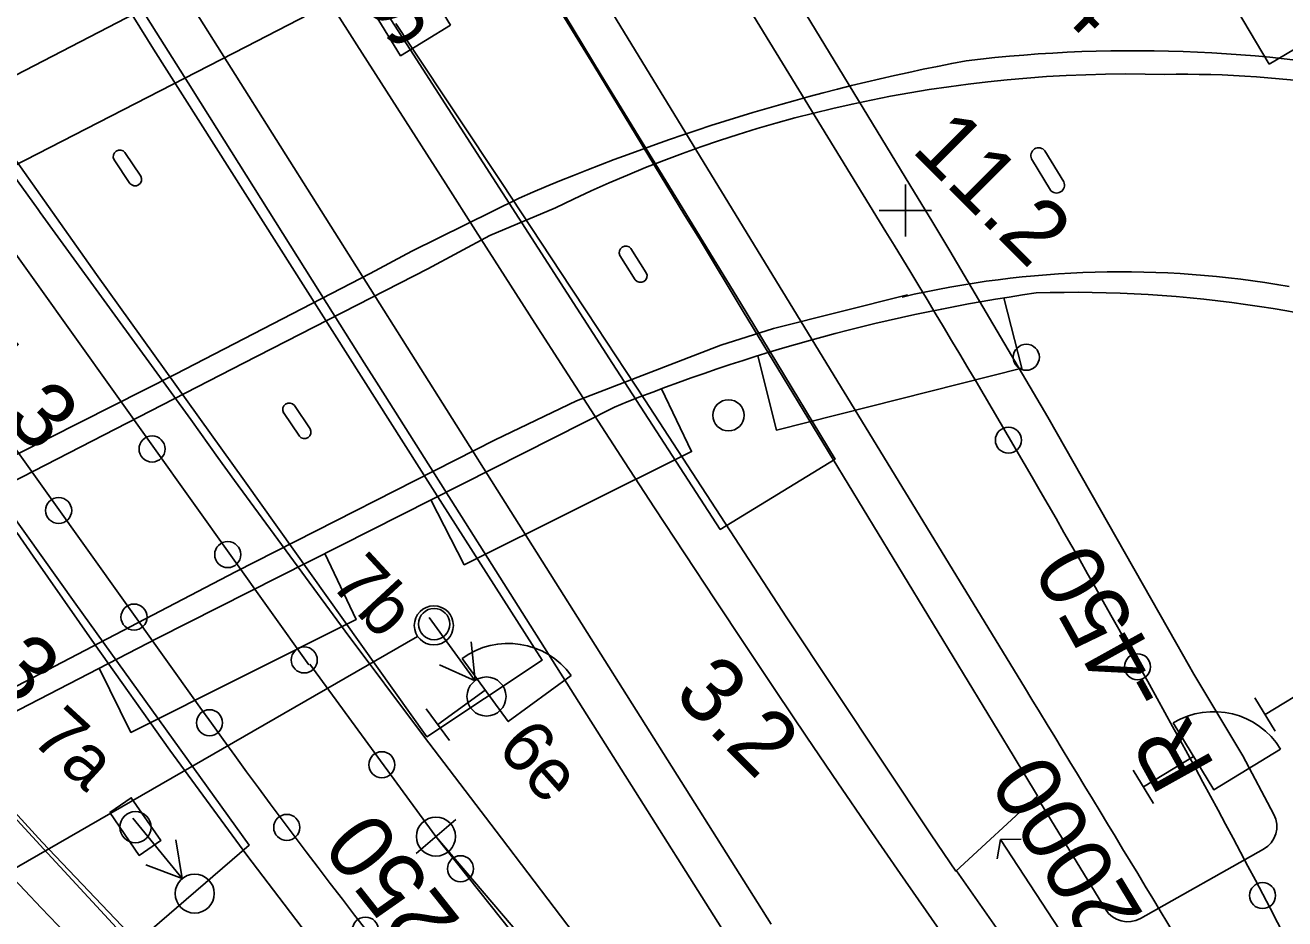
# Model space of a CAD drawing. Extents: x 1596643 to 1597288, y 13057194 to 13057957.
# Drawn here: x 1596850.68 to 1596899.03, y 13057506.23 to 13057540.55 of the extents above; entities that cross this region are included whole.
import ezdxf

# ---------------------------------------------------------------- set-up
doc = ezdxf.new("R2010")
doc.units = 0
for name, color, linetype in [('A Spårgeometri T', 7, 'Continuous'), ('A spårmitt L', 7, 'Continuous'), ('B Fsk P', 7, 'Continuous'), ('B kabelbrunn mindre än 150 cm NK P', 7, 'Continuous'), ('B växel linjevikt 0 L', 7, 'Continuous'), ('BAS bro ej def L', 7, 'Continuous'), ('BAS byggnad anläggning L', 7, 'Continuous'), ('BAS Level 14', 7, 'Continuous'), ('BAS Level 15', 7, 'Continuous'), ('BAS Level 16', 7, 'Continuous'), ('BAS markytetext T', 7, 'Continuous'), ('BAS skärmtak L', 7, 'Continuous'), ('BAS väg-bro pelare stöd L', 7, 'Continuous'), ('BAS vägbanekant L', 7, 'Continuous'), ('D Plattform L', 7, 'Continuous'), ('D plattform lastkaj -takstöd P', 7, 'Continuous'), ('D plattform tak L', 7, 'Continuous'), ('E ktlbrygga L', 7, 'Continuous'), ('E ktlstolpe normal centrum P', 7, 'Continuous'), ('E ktlstolpe omvriden centrum P', 7, 'Continuous'), ('E ktlstolpe T', 7, 'Continuous'), ('F dvärgsignal fristående P', 7, 'Continuous'), ('F tavla fristående P', 7, 'Continuous')]:
    doc.layers.add(name, color=color, linetype=linetype)

msp = doc.modelspace()

# ---------------------------------------------------------------- linework, layer by layer
at = {"layer": 'A spårmitt L'}
for p, q in [((1596861.568, 13057515.983), (1596783.022, 13057626.053)), ((1596889.034, 13057515.129), (1596838.504, 13057597.87)), ((1596879.311, 13057506.034), (1596843.07, 13057563.495))]:
    msp.add_line(p, q, dxfattribs=at)
for points in [[(1596857.385, 13057514.365), (1596753.204, 13057660.429)], [(1596883.716, 13057532.617), (1596844.805, 13057596.132)], [(1596886.686, 13057504.512), (1596885.471, 13057506.242), (1596884.265, 13057507.977), (1596883.065, 13057509.717), (1596881.872, 13057511.462), (1596880.686, 13057513.212), (1596879.507, 13057514.966), (1596878.333, 13057516.723), (1596877.164, 13057518.484), (1596876, 13057520.249), (1596874.841, 13057522.016), (1596873.686, 13057523.786), (1596872.535, 13057525.559), (1596871.387, 13057527.334), (1596870.242, 13057529.11), (1596869.099, 13057530.889), (1596867.959, 13057532.668), (1596866.82, 13057534.449), (1596865.683, 13057536.23), (1596864.546, 13057538.012), (1596863.41, 13057539.794), (1596846.221, 13057566.757)], [(1596861.603, 13057516.009), (1596866.442, 13057509.391), (1596878.849, 13057493.781), (1596895.097, 13057475.302), (1596900.34, 13057469.714), (1596931.231, 13057437.468), (1596933.8, 13057434.835)]]:
    msp.add_lwpolyline(points, dxfattribs=at)
for centre, radius, start, end in [((1597214.65, 13057850.135), 500, 218.04271, 224.75231), ((1596499.999, 13057297.54), 450, 26.52378, 31.49284), ((1597037.43, 13057725.326), 301.08, 223.02589, 237.32659), ((1595182.157, 13056472.741), 2000, 30.900492, 31.412375), ((1597060.917, 13057659.535), 250, 215.49853, 221.11206)]:
    msp.add_arc(centre, radius, start, end, dxfattribs=at)
at = {"layer": 'B Fsk P'}
msp.add_circle((1596866.447, 13057509.394), 0.75, dxfattribs=at)
msp.add_circle((1596866.447, 13057509.394), 0.75, dxfattribs=at)
at = {"layer": 'B kabelbrunn mindre än 150 cm NK P'}
msp.add_circle((1596889.108, 13057527.796), 0.5, dxfattribs=at)
msp.add_circle((1596889.108, 13057527.796), 0.5, dxfattribs=at)
at = {"layer": 'B växel linjevikt 0 L'}
for p, q in [((1596867.207, 13057510.044), (1596865.687, 13057508.744)), ((1596867.207, 13057510.044), (1596865.687, 13057508.744)), ((1596866.447, 13057509.394), (1596882.884, 13057490.154)), ((1596866.447, 13057509.394), (1596882.884, 13057490.154))]:
    msp.add_line(p, q, dxfattribs=at)
at = {"layer": 'BAS bro ej def L'}
for points in [[(1596943.383, 13057586.288), (1596918.209, 13057573.372), (1596902.266, 13057565.204), (1596883.836, 13057555.789), (1596868.629, 13057548.018), (1596857.404, 13057542.31), (1596846.034, 13057536.411), (1596835.657, 13057531.108), (1596827.266, 13057526.827), (1596817.271, 13057521.926), (1596816.146, 13057521.371), (1596813.704, 13057520.386), (1596810.367, 13057519.363)], [(1596873.3, 13057525.881), (1596855.752, 13057517.013), (1596837.576, 13057507.614), (1596820.661, 13057499.012), (1596812.839, 13057495.445), (1596806.321, 13057492.938), (1596797.787, 13057490.834), (1596791.903, 13057490.118), (1596786.013, 13057489.635), (1596782.527, 13057489.62), (1596780.068, 13057489.652), (1596778.301, 13057489.746), (1596776.535, 13057489.911), (1596771.663, 13057490.412), (1596770.466, 13057490.58)]]:
    msp.add_lwpolyline(points, dxfattribs=at)
for centre, radius, start, end in [((1596899.22, 13057462.24), 68.718, 98.1426, 112.16031), ((1596890.993, 13057483.825), 46.464, 70.6568, 91.8562)]:
    msp.add_arc(centre, radius, start, end, dxfattribs=at)
at = {"layer": 'BAS byggnad anläggning L'}
for points in [[(1596898.432, 13057539.054), (1596892.999, 13057548.2)], [(1596898.432, 13057539.054), (1596902.944, 13057541.738), (1596899.196, 13057548.047)]]:
    msp.add_lwpolyline(points, dxfattribs=at)
at = {"layer": 'BAS Level 14'}
for p, q in [((1596867.947, 13057515.378), (1596866.187, 13057517.808)), ((1596867.947, 13057515.378), (1596866.187, 13057517.808)), ((1596867.947, 13057515.378), (1596867.793, 13057516.87)), ((1596867.947, 13057515.378), (1596867.793, 13057516.87)), ((1596867.947, 13057515.378), (1596866.578, 13057515.991)), ((1596867.947, 13057515.378), (1596866.578, 13057515.991)), ((1596856.71, 13057507.783), (1596854.808, 13057510.102)), ((1596856.71, 13057507.783), (1596854.808, 13057510.102)), ((1596856.71, 13057507.783), (1596856.466, 13057509.263)), ((1596856.71, 13057507.783), (1596856.466, 13057509.263)), ((1596856.71, 13057507.783), (1596855.307, 13057508.312)), ((1596856.71, 13057507.783), (1596855.307, 13057508.312))]:
    msp.add_line(p, q, dxfattribs=at)
for centre in [(1596868.387, 13057514.771), (1596868.387, 13057514.771), (1596857.186, 13057507.203), (1596857.186, 13057507.203)]:
    msp.add_circle(centre, 0.75, dxfattribs=at)
at = {"layer": 'BAS Level 15'}
for centre in [(1596888.421, 13057524.613), (1596888.421, 13057524.613), (1596855.549, 13057524.274), (1596855.549, 13057524.274), (1596851.964, 13057521.911), (1596851.964, 13057521.911), (1596858.454, 13057520.219), (1596858.454, 13057520.219), (1596854.856, 13057517.82), (1596854.856, 13057517.82), (1596861.392, 13057516.173), (1596861.392, 13057516.173), (1596893.375, 13057515.912), (1596893.375, 13057515.912), (1596857.755, 13057513.763), (1596857.755, 13057513.763), (1596864.368, 13057512.15), (1596864.368, 13057512.15), (1596860.719, 13057509.745), (1596860.719, 13057509.745), (1596867.388, 13057508.158), (1596867.388, 13057508.158), (1596898.176, 13057507.128), (1596898.176, 13057507.128), (1596863.738, 13057505.801), (1596863.738, 13057505.801)]:
    msp.add_circle(centre, 0.5, dxfattribs=at)
at = {"layer": 'BAS Level 16'}
for q in [(1596884.465, 13057534.433), (1596884.465, 13057534.433), (1596883.465, 13057533.433), (1596883.465, 13057533.433), (1596885.465, 13057533.433), (1596884.465, 13057532.433), (1596885.465, 13057533.433), (1596884.465, 13057532.433)]:
    msp.add_line((1596884.465, 13057533.433), q, dxfattribs=at)
at = {"layer": 'BAS skärmtak L'}
for points in [[(1596888.241, 13057530.074), (1596888.937, 13057527.373), (1596879.514, 13057525.003), (1596878.798, 13057527.853)], [(1596875.104, 13057526.586), (1596876.257, 13057524.176), (1596867.535, 13057519.831), (1596866.251, 13057522.319)], [(1596862.187, 13057520.265), (1596863.387, 13057517.728), (1596854.736, 13057513.393), (1596853.523, 13057515.86)]]:
    msp.add_lwpolyline(points, dxfattribs=at)
at = {"layer": 'BAS väg-bro pelare stöd L'}
for p, q in [((1596854.508, 13057535.659), (1596855.114, 13057534.751)), ((1596889.821, 13057535.721), (1596890.543, 13057534.528)), ((1596854.092, 13057535.381), (1596854.698, 13057534.473)), ((1596889.308, 13057535.41), (1596890.03, 13057534.217)), ((1596874.098, 13057530.77), (1596873.51, 13057531.702)), ((1596873.933, 13057531.969), (1596874.521, 13057531.037)), ((1596861.012, 13057525.949), (1596861.621, 13057525.047)), ((1596860.598, 13057525.669), (1596861.207, 13057524.767))]:
    msp.add_line(p, q, dxfattribs=at)
for points in [[(1596854.508, 13057535.659), (1596855.114, 13057534.751)], [(1596889.821, 13057535.721), (1596890.543, 13057534.528)], [(1596854.092, 13057535.381), (1596854.698, 13057534.473)], [(1596889.308, 13057535.41), (1596890.03, 13057534.217)], [(1596874.098, 13057530.77), (1596873.51, 13057531.702)], [(1596873.933, 13057531.969), (1596874.521, 13057531.037)], [(1596861.012, 13057525.949), (1596861.621, 13057525.047)], [(1596860.598, 13057525.669), (1596861.207, 13057524.767)]]:
    msp.add_lwpolyline(points, dxfattribs=at)
for centre, radius, start, end in [((1596854.311, 13057535.503), 0.251, 38.4145, 209.0926), ((1596854.311, 13057535.503), 0.251, 38.3749, 209.1212), ((1596889.582, 13057535.535), 0.302, 37.7798, 204.5846), ((1596889.583, 13057535.535), 0.302, 38.0081, 204.444), ((1596854.894, 13057534.629), 0.251, 218.4145, 29.0926), ((1596854.895, 13057534.629), 0.251, 218.3749, 29.1212), ((1596890.268, 13057534.402), 0.302, 217.7798, 24.5846), ((1596890.268, 13057534.403), 0.302, 218.0081, 24.444), ((1596873.733, 13057531.817), 0.251, 37.0895, 207.4312), ((1596874.298, 13057530.921), 0.251, 217.0895, 27.4312), ((1596860.818, 13057525.79), 0.251, 39.3376, 208.8108), ((1596860.818, 13057525.789), 0.251, 39.4426, 208.7006), ((1596861.401, 13057524.926), 0.251, 219.4426, 28.7006), ((1596861.401, 13057524.926), 0.251, 219.3376, 28.8108)]:
    msp.add_arc(centre, radius, start, end, dxfattribs=at)
at = {"layer": 'BAS vägbanekant L'}
for points in [[(1596968.373, 13057595.733), (1596951.07, 13057586.844), (1596934.686, 13057578.377), (1596919.638, 13057570.696), (1596906.067, 13057563.73), (1596892.75, 13057556.935), (1596882.725, 13057551.852), (1596869.694, 13057545.167), (1596859.148, 13057539.721), (1596850.202, 13057535.12), (1596841.053, 13057530.419), (1596829.938, 13057524.843), (1596820.555, 13057520.234), (1596817.458, 13057518.694), (1596815.33, 13057517.841), (1596812.855, 13057516.796), (1596811.578, 13057516.307)], [(1596869.647, 13057533.909), (1596865.516, 13057531.872), (1596863.915, 13057531.016), (1596856.445, 13057527.152), (1596846.765, 13057522.254), (1596837.481, 13057517.607), (1596829.288, 13057513.503), (1596822.227, 13057510.094), (1596818.621, 13057508.395), (1596812.116, 13057505.786)], [(1596871.037, 13057533.536), (1596868.517, 13057532.466), (1596866.132, 13057531.188), (1596859.059, 13057527.566), (1596850.581, 13057523.209), (1596840.584, 13057518.17), (1596831.382, 13057513.482), (1596826.297, 13057511.029), (1596823.668, 13057509.721), (1596819.532, 13057507.842), (1596812.775, 13057505.098)], [(1596884.542, 13057530.19), (1596879.403, 13057528.895), (1596877.377, 13057528.265), (1596871.837, 13057526.129), (1596868.719, 13057524.621), (1596858.752, 13057519.551), (1596850.365, 13057515.184), (1596847.614, 13057513.846), (1596841.051, 13057510.466), (1596834.743, 13057507.226), (1596828.139, 13057503.724), (1596822.677, 13057500.978), (1596818.182, 13057498.582), (1596816.389, 13057497.809), (1596813.852, 13057496.593), (1596810.012, 13057494.926)]]:
    msp.add_lwpolyline(points, dxfattribs=at)
for centre, radius, start, end in [((1596893.232, 13057485.798), 53.769, 77.9076, 96.8735), ((1596901.685, 13057460.224), 80.349, 100.67822, 113.49925), ((1596893.112, 13057488.684), 49.99, 88.4927, 116.2052), ((1596895.129, 13057499.432), 39.231, 70.5134, 91.0268), ((1596892.758, 13057494.11), 36.969, 79.9774, 103.157)]:
    msp.add_arc(centre, radius, start, end, dxfattribs=at)
at = {"layer": 'D Plattform L'}
for p, q in [((1596864.91, 13057540.617), (1596865.482, 13057539.743)), ((1596857.411, 13057537.573), (1596858.034, 13057536.578)), ((1596851.25, 13057533.356), (1596851.933, 13057532.416)), ((1596876, 13057533.243), (1596876.559, 13057532.337)), ((1596885.481, 13057533.037), (1596886.173, 13057531.887)), ((1596871.632, 13057530.455), (1596872.233, 13057529.543)), ((1596863.697, 13057527.588), (1596864.26, 13057526.7)), ((1596858.073, 13057523.943), (1596858.71, 13057523.059)), ((1596850.359, 13057521.065), (1596850.982, 13057520.161)), ((1596888.111, 13057509.274), (1596887.992, 13057508.539)), ((1596888.91, 13057509.287), (1596888.111, 13057509.274)), ((1596891.297, 13057504.419), (1596888.111, 13057509.274)), ((1596889.462, 13057503.75), (1596886.428, 13057508.08))]:
    msp.add_line(p, q, dxfattribs=at)
for points in [[(1596857.411, 13057537.573), (1596856.94, 13057538.339), (1596851.591, 13057546.812), (1596846.254, 13057555.223), (1596840.88, 13057563.665), (1596835.507, 13057572.103), (1596830, 13057580.514), (1596824.426, 13057588.811)], [(1596816.353, 13057582.272), (1596822.143, 13057574.145), (1596827.93, 13057566.016), (1596833.757, 13057557.837), (1596839.529, 13057549.736), (1596845.34, 13057541.563), (1596851.179, 13057533.468), (1596851.25, 13057533.356)], [(1596877.921, 13057545.439), (1596879.58, 13057542.733), (1596884.821, 13057534.118), (1596885.481, 13057533.037)], [(1596876, 13057533.243), (1596872.512, 13057538.997), (1596870.258, 13057542.674)], [(1596865.482, 13057539.743), (1596868.966, 13057534.502), (1596871.632, 13057530.455)], [(1596858.034, 13057536.578), (1596862.264, 13057529.864), (1596863.697, 13057527.588)], [(1596858.073, 13057523.943), (1596857.036, 13057525.403), (1596854.119, 13057529.415), (1596851.933, 13057532.416)], [(1596872.233, 13057529.543), (1596874.469, 13057526.162), (1596879.921, 13057517.786), (1596885.455, 13057509.461), (1596886.408, 13057508.058), (1596889.541, 13057510.954), (1596888.606, 13057512.507), (1596883.425, 13057521.032), (1596878.241, 13057529.552), (1596876.559, 13057532.337)], [(1596886.173, 13057531.887), (1596889.931, 13057525.497), (1596894.883, 13057516.78), (1596895.535, 13057515.627), (1596897.421, 13057512.491)], [(1596864.26, 13057526.7), (1596867.582, 13057521.437), (1596872.945, 13057512.951), (1596878.283, 13057504.508), (1596879.469, 13057502.624)], [(1596876.006, 13057500.307), (1596874.935, 13057501.4), (1596871.998, 13057505.344), (1596868.969, 13057509.328), (1596865.966, 13057513.26), (1596862.965, 13057517.282), (1596858.71, 13057523.059)], [(1596850.982, 13057520.161), (1596853.321, 13057516.805), (1596856.235, 13057512.713), (1596859.19, 13057508.682), (1596862.296, 13057504.59), (1596865.339, 13057500.75), (1596868.682, 13057496.703), (1596868.901, 13057496.442)], [(1596866.296, 13057493.938), (1596865.277, 13057494.926), (1596858.22, 13057501.943), (1596851.337, 13057509.173), (1596845.311, 13057515.752)], [(1596898.608, 13057510.243), (1596897.421, 13057512.491)], [(1596889.658, 13057510.693), (1596892.149, 13057506.599)], [(1596893.494, 13057506.247), (1596898.214, 13057508.905)]]:
    msp.add_lwpolyline(points, dxfattribs=at)
for centre, start, end in [((1596897.723, 13057509.776), 299.3796, 27.8335), ((1596893.003, 13057507.119), 211.3106, 299.3796)]:
    msp.add_arc(centre, 1, start, end, dxfattribs=at)
at = {"layer": 'D plattform lastkaj -takstöd P'}
for centre in [(1596877.674, 13057525.567), (1596877.674, 13057525.567), (1596866.376, 13057517.552), (1596866.376, 13057517.552), (1596854.911, 13057509.753), (1596854.911, 13057509.753)]:
    msp.add_circle(centre, 0.6, dxfattribs=at)
at = {"layer": 'D plattform tak L'}
for points in [[(1596831.126, 13057606.75), (1596836.548, 13057598.096), (1596842.024, 13057589.089), (1596847.474, 13057580.219), (1596852.049, 13057572.706), (1596856.959, 13057564.707), (1596862.361, 13057555.86), (1596867.644, 13057547.153), (1596872.794, 13057538.633), (1596878.134, 13057529.883), (1596881.766, 13057523.887), (1596877.359, 13057521.189), (1596873.222, 13057527.561), (1596867.885, 13057535.835), (1596862.418, 13057544.331), (1596857.123, 13057552.678), (1596851.671, 13057561.115), (1596846.248, 13057569.545), (1596840.785, 13057577.951), (1596835.301, 13057586.253), (1596829.72, 13057594.575), (1596824.028, 13057602.822)], [(1596811.914, 13057606.395), (1596817.73, 13057598.196), (1596823.263, 13057590.081), (1596828.74, 13057581.904), (1596834.285, 13057573.531), (1596839.64, 13057565.192), (1596845.068, 13057556.556), (1596850.326, 13057548.152), (1596855.605, 13057539.631), (1596860.931, 13057531.243), (1596866.314, 13057522.755), (1596870.525, 13057516.168), (1596866.099, 13057513.223), (1596859.096, 13057523.047), (1596853.418, 13057530.972), (1596847.483, 13057539.363), (1596841.689, 13057547.404), (1596835.835, 13057555.629), (1596830.041, 13057563.74), (1596824.185, 13057571.89), (1596818.331, 13057580.068), (1596812.671, 13057587.955), (1596806.635, 13057596.366), (1596800.989, 13057604.259)], [(1596791.643, 13057603.754), (1596794.543, 13057599.677), (1596800.292, 13057591.62), (1596806.147, 13057583.416), (1596811.988, 13057575.257), (1596817.843, 13057567.087), (1596823.598, 13057559.058), (1596826.007, 13057555.757), (1596826.02, 13057555.684), (1596829.426, 13057550.911), (1596835.25, 13057542.713), (1596840.981, 13057534.653), (1596846.813, 13057526.461), (1596852.619, 13057518.322), (1596859.283, 13057509.064), (1596854.815, 13057505.213), (1596851.39, 13057508.912), (1596844.685, 13057516.187), (1596838.116, 13057523.683), (1596831.752, 13057531.187), (1596825.407, 13057538.897), (1596819.262, 13057546.672), (1596816.697, 13057550.092), (1596826.02, 13057555.684)]]:
    msp.add_lwpolyline(points, dxfattribs=at)
at = {"layer": 'E ktlbrygga L'}
msp.add_lwpolyline([(1596865.744, 13057517.08), (1596841.758, 13057503.265)], dxfattribs=at)
at = {"layer": 'E ktlstolpe normal centrum P'}
msp.add_circle((1596866.366, 13057517.499), 0.75, dxfattribs=at)
msp.add_circle((1596866.366, 13057517.499), 0.75, dxfattribs=at)
at = {"layer": 'E ktlstolpe omvriden centrum P'}
msp.add_lwpolyline([(1596853.925, 13057510.318), (1596854.748, 13057510.884), (1596855.883, 13057509.237), (1596855.059, 13057508.67)], close=True, dxfattribs=at)
msp.add_lwpolyline([(1596853.925, 13057510.318), (1596854.748, 13057510.884), (1596855.883, 13057509.237), (1596855.059, 13057508.67)], close=True, dxfattribs=at)
at = {"layer": 'F dvärgsignal fristående P'}
for p, q in [((1596900.199, 13057515.251), (1596898.275, 13057514.084)), ((1596900.199, 13057515.251), (1596898.275, 13057514.084)), ((1596868.336, 13057515.018), (1596866.52, 13057513.69)), ((1596868.336, 13057515.018), (1596866.52, 13057513.69)), ((1596897.886, 13057514.725), (1596898.664, 13057513.443)), ((1596897.886, 13057514.725), (1596898.664, 13057513.443)), ((1596866.077, 13057514.295), (1596866.963, 13057513.085)), ((1596866.077, 13057514.295), (1596866.963, 13057513.085)), ((1596895.527, 13057512.472), (1596893.603, 13057511.305)), ((1596895.527, 13057512.472), (1596893.603, 13057511.305)), ((1596893.214, 13057511.946), (1596893.992, 13057510.664)), ((1596893.214, 13057511.946), (1596893.992, 13057510.664))]:
    msp.add_line(p, q, dxfattribs=at)
for points in [[(1596867.451, 13057516.229), (1596869.222, 13057513.807), (1596871.643, 13057515.578)], [(1596867.451, 13057516.229), (1596869.222, 13057513.807), (1596871.643, 13057515.578)], [(1596894.748, 13057513.755), (1596896.305, 13057511.19), (1596898.869, 13057512.746)], [(1596894.748, 13057513.755), (1596896.305, 13057511.19), (1596898.869, 13057512.746)]]:
    msp.add_lwpolyline(points, dxfattribs=at)
for centre, start, end in [((1596869.221, 13057513.807), 36.1738, 126.1738), ((1596869.221, 13057513.807), 36.1738, 126.1738), ((1596896.305, 13057511.19), 31.2508, 121.2508), ((1596896.305, 13057511.19), 31.2508, 121.2508)]:
    msp.add_arc(centre, 3, start, end, dxfattribs=at)
at = {"layer": 'F tavla fristående P'}
msp.add_lwpolyline([(1596867.008, 13057540.546), (1596865.445, 13057543.105), (1596863.524, 13057541.933), (1596865.088, 13057539.373)], close=True, dxfattribs=at)

# ---------------------------------------------------------------- texts
at = {"layer": 'A Spårgeometri T'}
for s, rotation, p in [('R -450', 119.016, (1596896.39, 13057512.078)), ('R -2000', 121.158, (1596895.954, 13057502.562)), ('R 250', 128.313, (1596869.526, 13057503.512))]:
    msp.add_text(s, height=2.5, rotation=rotation, dxfattribs=at).set_placement(p)
at = {"layer": 'BAS markytetext T'}
for s, p in [('11.4', (1596886.809, 13057544.547)), ('11.2', (1596884.651, 13057535.737)), ('11.3', (1596846.565, 13057528.642)), ('11.3', (1596845.86, 13057518.943)), ('3.2', (1596875.519, 13057514.802))]:
    msp.add_text(s, height=2.5, rotation=315, dxfattribs=at).set_placement(p)
at = {"layer": 'E ktlstolpe T'}
for s, rotation, p in [('7b', 312.8018, (1596862.328, 13057519.084)), ('7a', 317.4351, (1596850.844, 13057513.08)), ('6e', 311.8095, (1596868.734, 13057512.757))]:
    msp.add_text(s, height=1.999, rotation=rotation, dxfattribs=at).set_placement(p)
at = {"layer": 'F tavla fristående P'}
msp.add_text('S', height=2.25, rotation=211.4079, dxfattribs=at).set_placement((1596865.192, 13057542.512))
msp.add_text('S', height=2.25, rotation=211.4079, dxfattribs=at).set_placement((1596865.192, 13057542.512))

doc.saveas('drawing.dxf')
